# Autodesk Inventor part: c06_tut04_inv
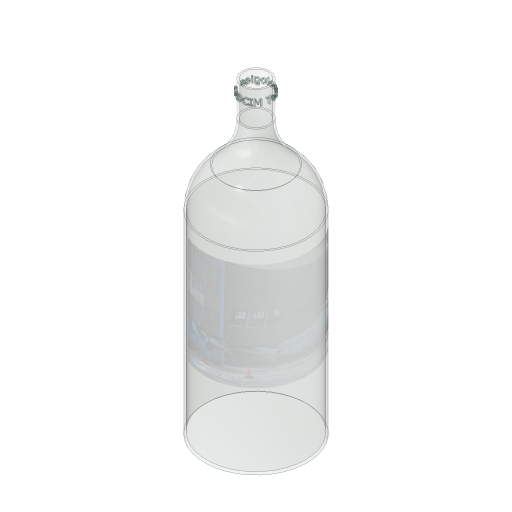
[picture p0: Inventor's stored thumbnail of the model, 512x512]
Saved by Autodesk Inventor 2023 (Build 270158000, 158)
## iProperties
Created: 2015-03
Part Number: c06_tut04_inv
Material: Glass
Document SubType Name: Modeling
Designer: Sandeep
Density: 2.18 g/cm^3
Appearance: Clear
Author: Sandeep
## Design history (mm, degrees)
sketch "Sketch1"
  geometry: L1 (8, 180)-(8, 160); L2 (30, 113.567)-(30, 0); L3 (30, 0)-(0, 0); L4 (0, 0)-(0, -98.027); L5 (7, 180)-(7, 160); L6 (29, 113.567)-(29, 1); L7 (29, 1)-(0, 1); L8 (8, 180)-(7, 180); L9 (0, 1)-(0, 0); A1 r 30 centre (38, 160) between (8, 160) and (19, 136.784); A2 r 30 centre (0, 113.567) between (30, 113.567) and (19, 136.784); A3 r 31 centre (38, 160) between (7, 160) and (18.367, 136.01); A4 r 29 centre (0, 113.567) between (29, 113.567) and (18.367, 136.01)
  constraints: 18 end point, 8 point on circle, 4 centre point, 3 perpendicular, 3 tangent, 2 parallel, 2 vertical, 1 horizontal, 4 other
  dimensions: "d0" = 20 distance of L1.start L1.end; "d1" = 30 radius of A1; "d2" = 30 radius of A2; "d7" = 180 vertical distance of L3.end L1.start; "d17" = 1 distance between parallel lines of L5 L1; "d18" = 60 diameter of L2 L4; "d19" = 16 diameter of L1 L4
revolve "Revolution1" sketch "Sketch1" stored, may be unused: angle "d9" = 90 deg
workplane "Work Plane1"
sketch "Sketch2"
  geometry: L1 (-21.117, 118.431)-(137.947, 118.431); L2 (137.947, 118.431)-(137.947, 105.984); L3 (137.947, 105.984)-(-21.117, 105.984); L4 (-21.117, 105.984)-(-21.117, 118.431); 1 further point
  constraints: 2 other
emboss "Emboss1" sketch "Sketch2" dims "d1" = 30, "d10" = 1, "d11" = 0
sketch "Sketch3"
  geometry: L1 (-60.338, 49.443)-(58.204, 49.443); L2 (58.204, 49.443)-(58.204, -13.263); L3 (58.204, -13.263)-(-60.338, -13.263); L4 (-60.338, -13.263)-(-60.338, 49.443); 1 further point; 1 other entity
  constraints: 2 other
feature "Decal1" sketch "Sketch3"
body "Solid1"
node "Image1"
